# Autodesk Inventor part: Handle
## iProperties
Shininess: 0.0
Length Units: 11272
Angle Units: 11279
Time Units: 11290
Mass Units: 11283
Length Display Precision: 2
Angle Display Precision: 1
Created: 1999-05
Part Number: Handle
Document SubType Name: Modeling
Designer: Administrator
Density: 1 g/cm^3
Density: 0.0
Volumn: 0.0
Area: 0.0
PropertySet Name: Model Information
Control State: 0
Master: False
Checked Out: False
Author: Administrator
